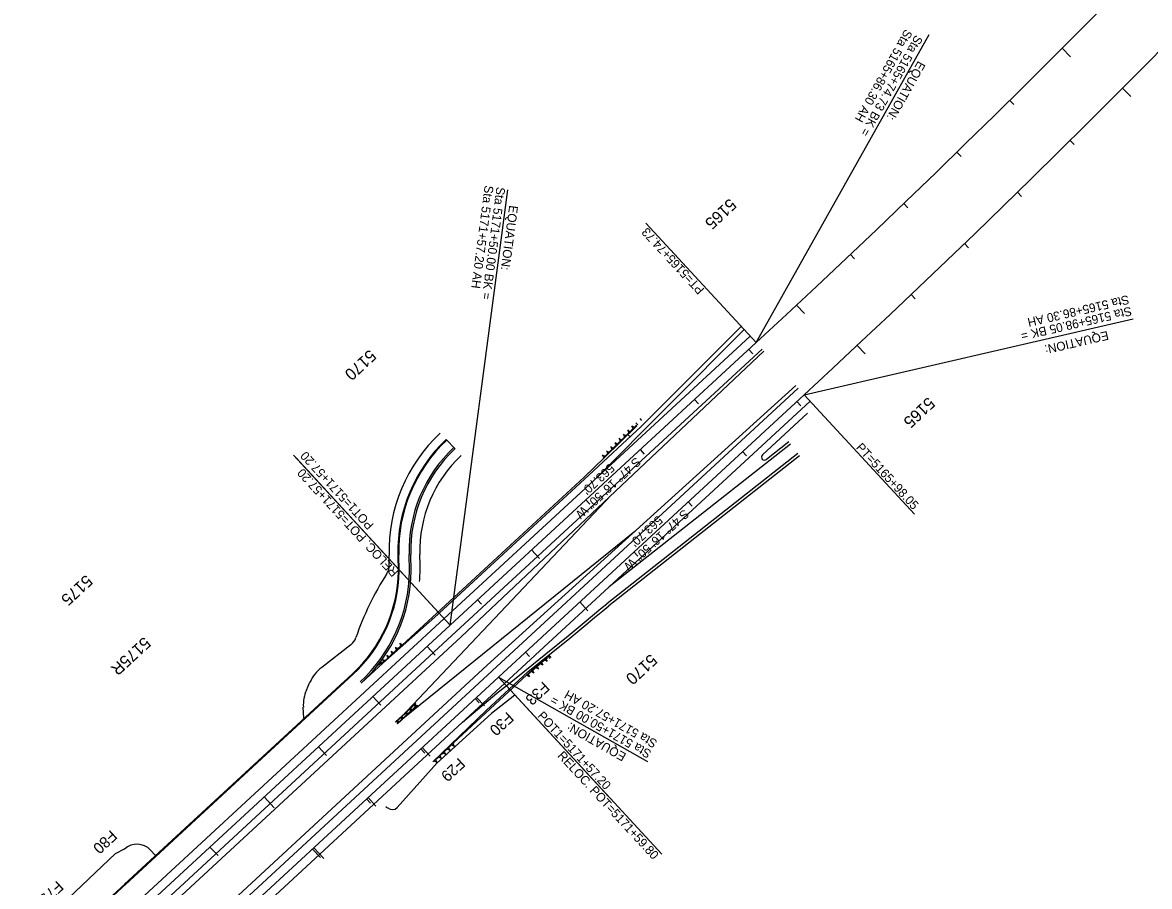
# Model space of a CAD drawing. Extents: x 2160877 to 2175861, y 601747 to 617724.
# Drawn here: x 2171628 to 2173154, y 613421 to 614591 of the extents above; entities that cross this region are included whole.
import ezdxf

# ---------------------------------------------------------------- set-up
doc = ezdxf.new("R2010")
doc.units = 0
for name, color, linetype in [('RD_HC_Cl', 7, 'Continuous'), ('RD_HC_CL_Rel', 7, 'Continuous'), ('RD_HC_Data', 7, 'Continuous'), ('RD_HC_Data_Rel', 7, 'Continuous'), ('RD_HC_Data_Tic', 7, 'Continuous'), ('RD_HC_Data_Tic_Rel', 7, 'Continuous'), ('RD_HC_TX_Rel_Sta50', 7, 'Continuous'), ('RD_HC_TX_StaOther', 7, 'Continuous'), ('RD_PD_CstnLmt', 7, 'Continuous'), ('RD_PD_CstnLmt_TX', 7, 'Continuous'), ('RD_PD_Final_LnLine', 7, 'Continuous'), ('RD_PD_Final_TrvlWay', 7, 'Continuous'), ('RD_PD_GR', 7, 'Continuous'), ('RD_PD_MedBWall', 7, 'Continuous')]:
    doc.layers.add(name, color=color, linetype=linetype)

msp = doc.modelspace()

# ---------------------------------------------------------------- linework, layer by layer
at = {"layer": 'RD_HC_Cl'}
for p, q in [((2172621.5, 614157.6), (2172207.3, 613775.1)), ((2172686.6, 614087), (2172272.5, 613704.6)), ((2172207.3, 613775.1), (2163672.2, 605893.8)), ((2172272.5, 613704.6), (2163737.4, 605823.3))]:
    msp.add_line(p, q, dxfattribs=at)
for radius, end in [(14276, 327.03525), (14372, 326.23563)]:
    msp.add_arc((2162936.5, 624645.9), radius, 312.71947, end, dxfattribs=at)
at = {"layer": 'RD_HC_CL_Rel'}
for p, q in [((2172207.3, 613775.1), (2171340.7, 612974.9)), ((2172272.5, 613704.6), (2170771.4, 612318.6))]:
    msp.add_line(p, q, dxfattribs=at)
at = {"layer": 'RD_HC_Data'}
for p, q in [((2172621.5, 614157.6), (2172855.6, 614574.5)), ((2172207.3, 613775.1), (2172285.1, 614364.1)), ((2172621.5, 614157.6), (2172472.2, 614319.2)), ((2172686.6, 614087), (2173132, 614189.8)), ((2172686.6, 614087), (2172836, 613925.2)), ((2172207.3, 613775.1), (2171994.9, 614005.2)), ((2172272.5, 613704.6), (2172474.3, 613590.3)), ((2172272.5, 613704.6), (2172421.7, 613543))]:
    msp.add_line(p, q, dxfattribs=at)
at = {"layer": 'RD_HC_Data_Rel'}
for p, q in [((2172207.3, 613775.1), (2171998.5, 614001.3)), ((2172272.5, 613704.6), (2172493.8, 613464.9))]:
    msp.add_line(p, q, dxfattribs=at)
at = {"layer": 'RD_HC_Data_Tic'}
for p, q in [((2173035.7, 614555.9), (2173047.1, 614544.5)), ((2173117.4, 614501.8), (2173128.7, 614490.5)), ((2172964.8, 614485.4), (2172970.4, 614479.7)), ((2173046.6, 614431.2), (2173052.2, 614425.5)), ((2172893.4, 614415.4), (2172899, 614409.6)), ((2172975.3, 614361.1), (2172980.8, 614355.4)), ((2172821.5, 614345.9), (2172827, 614340.1)), ((2172903.5, 614291.5), (2172909, 614285.7)), ((2172749.1, 614276.9), (2172754.6, 614271.1)), ((2172831.2, 614222.4), (2172836.7, 614216.6)), ((2172676.2, 614208.4), (2172687.2, 614196.7)), ((2172758.4, 614153.8), (2172769.3, 614142.1)), ((2172611.4, 614148.3), (2172616.8, 614142.4)), ((2172537.9, 614080.4), (2172543.4, 614074.5)), ((2172676.5, 614077.7), (2172682, 614071.9)), ((2172464.5, 614012.6), (2172469.9, 614006.7)), ((2172603.1, 614009.9), (2172608.5, 614004)), ((2172391, 613944.7), (2172396.4, 613938.9)), ((2172529.6, 613942.1), (2172535, 613936.2)), ((2172317.5, 613876.9), (2172328.4, 613865.1)), ((2172456.1, 613874.2), (2172461.5, 613868.3)), ((2172244.1, 613809.1), (2172249.5, 613803.2)), ((2172382.7, 613806.4), (2172393.5, 613794.6)), ((2172175.9, 613746.1), (2172181.3, 613740.2)), ((2172309.2, 613738.5), (2172314.6, 613732.7)), ((2172102.4, 613678.3), (2172107.8, 613672.4)), ((2172241, 613675.6), (2172246.4, 613669.7)), ((2172028.9, 613610.4), (2172034.4, 613604.5)), ((2172167.5, 613607.7), (2172173, 613601.9)), ((2171955.5, 613542.6), (2171966.3, 613530.8)), ((2172094.1, 613539.9), (2172099.5, 613534)), ((2171882, 613474.7), (2171887.4, 613468.9)), ((2172020.6, 613472.1), (2172031.5, 613460.3))]:
    msp.add_line(p, q, dxfattribs=at)
at = {"layer": 'RD_HC_Data_Tic_Rel'}
for p, q in [((2172175.9, 613746.1), (2172186.7, 613734.4)), ((2172102.4, 613678.3), (2172113.3, 613666.5)), ((2172242.9, 613677.3), (2172253.8, 613665.6)), ((2172028.9, 613610.4), (2172039.8, 613598.7)), ((2172169.4, 613609.5), (2172180.3, 613597.7)), ((2171955.5, 613542.6), (2171969, 613527.9)), ((2172096, 613541.7), (2172106.8, 613529.9)), ((2171882, 613474.7), (2171892.9, 613463)), ((2172022.5, 613473.8), (2172036.1, 613459.1))]:
    msp.add_line(p, q, dxfattribs=at)
at = {"layer": 'RD_PD_CstnLmt'}
for p, q in [((2172124.8, 613856.2), (2172124.5, 613869.7)), ((2172166.4, 613856.6), (2172166.1, 613870.7)), ((2172072.6, 613748.5), (2172033.5, 613717.8)), ((2172012.7, 613687), (2172017.4, 613697.8)), ((2172294.8, 613680.4), (2172263.1, 613655.5)), ((2172009.3, 613648.9), (2172008.4, 613664.1)), ((2172263.1, 613655.5), (2172189.1, 613588.3)), ((2172135.6, 613528.1), (2172189.1, 613588.3)), ((2172120, 613529.7), (2172122.6, 613527.6)), ((2171754.2, 613465.7), (2171681.6, 613397)), ((2171754.2, 613465.7), (2171766.2, 613472)), ((2171807.8, 613463.6), (2171801.4, 613470.5))]:
    msp.add_line(p, q, dxfattribs=at)
for centre, radius, start, end in [((2172343.7, 613875.1), 219.3, 133.1773, 181.4209), ((2172343.7, 613875.1), 177.7, 133.1773, 181.4209), ((2172104.8, 613855.7), 20, 327.0543, 1.4209), ((2171944.2, 613851.1), 222.3, 355.5815, 1.4209), ((2172447.7, 613633.5), 388.6, 147.0543, 161.2766), ((2172060.7, 613764.6), 20, 306.2944, 341.2766), ((2172063.1, 613677.5), 50, 126.2944, 156.1048), ((2172058.4, 613666.8), 50, 156.1048, 183.118), ((2172128.8, 613535.4), 10, 231.8554, 312.7195), ((2171783.1, 613453.5), 25, 42.7195, 132.3521)]:
    msp.add_arc(centre, radius, start, end, dxfattribs=at)
at = {"layer": 'RD_PD_Final_LnLine'}
for p, q in [((2172605.3, 614175.1), (2172401.6, 613970.8)), ((2172613.3, 614166.4), (2172401.6, 613970.8)), ((2172629.6, 614148.7), (2172215.5, 613766.3)), ((2172678.5, 614095.8), (2172264.3, 613713.4)), ((2172694.7, 614078.2), (2172422.5, 613826.8)), ((2172668, 614019.9), (2172422.5, 613826.8)), ((2172677.9, 614007.4), (2172419.4, 613804.1)), ((2172401.6, 613970.8), (2172199.2, 613784)), ((2172425.3, 613950.8), (2172140.7, 613650.6)), ((2172457.4, 613901.8), (2172143, 613648.1)), ((2172422.5, 613826.8), (2172222.3, 613642.1)), ((2172199.2, 613784), (2171332.6, 612983.8)), ((2172215.5, 613766.3), (2171348.9, 612966.1)), ((2172115.9, 613723.4), (2172086.9, 613696.6)), ((2172114.3, 613725.1), (2172108.2, 613719.4)), ((2172114.3, 613725.1), (2172115.9, 613723.4)), ((2172264.3, 613713.4), (2170763.3, 612327.4)), ((2172224.1, 613643.7), (2170779.6, 612309.8))]:
    msp.add_line(p, q, dxfattribs=at)
msp.add_lwpolyline([(2172224.1, 613643.7), (2172270.5, 613682.8), (2172284.9, 613694.4), (2172308.1, 613713.2), (2172336.9, 613736.4), (2172366.9, 613760.6), (2172388.6, 613778.6), (2172400.1, 613788.2), (2172411.3, 613797.7), (2172419.4, 613804.1)], dxfattribs=at)
at = {"layer": 'RD_PD_Final_TrvlWay'}
for p, q in [((2172601.2, 614179.5), (2172466, 614044)), ((2172632, 614146.1), (2172222.2, 613759)), ((2172675.3, 614099.3), (2172257.5, 613720.8)), ((2172691.2, 614061.8), (2172630.2, 614005.4)), ((2172466, 614044), (2172394.8, 613978.2)), ((2172665.6, 614023.1), (2172635.4, 613999.3)), ((2172680.4, 614004.2), (2172422.2, 613801.1)), ((2172394.8, 613978.2), (2172192.4, 613791.3)), ((2172190.4, 613789.4), (2172115.9, 613723.4)), ((2172192.4, 613791.3), (2172190.4, 613789.4)), ((2172222.2, 613759), (2171355.7, 612958.8)), ((2172257.5, 613720.8), (2170756.5, 612334.7)), ((2172312.6, 613711.7), (2172255.9, 613659.4)), ((2172255.9, 613659.4), (2172183.8, 613590.1))]:
    msp.add_line(p, q, dxfattribs=at)
msp.add_lwpolyline([(2172312.6, 613711.7), (2172369.4, 613757.5), (2172391.1, 613775.5), (2172402.7, 613785.2), (2172413.8, 613794.6), (2172422.2, 613801.1)], dxfattribs=at)
msp.add_arc((2172632.9, 614002.5), 4, 132.7195, 308.1849, dxfattribs=at)
at = {"layer": 'RD_PD_GR'}
for p, q in [((2172458.8, 614044.7), (2172415.3, 614001.9)), ((2172415.6, 614001.5), (2172459.8, 614045)), ((2172454.2, 614044.7), (2172452.9, 614043.5)), ((2172454.4, 614043.2), (2172453.5, 614044.1)), ((2172453.8, 614042.6), (2172455, 614043.8)), ((2172455, 614043.8), (2172456.4, 614042.4)), ((2172459.1, 614045.7), (2172458.4, 614045)), ((2172458.4, 614045), (2172458.8, 614044.7)), ((2172461.2, 614046.4), (2172458.6, 614049.1)), ((2172459.8, 614045), (2172459.1, 614045.7)), ((2172466.9, 614052), (2172464.3, 614054.7)), ((2172442.8, 614033.5), (2172441.5, 614032.2)), ((2172443, 614032), (2172442.1, 614032.9)), ((2172442.4, 614031.4), (2172443.6, 614032.6)), ((2172443.8, 614029.9), (2172442.4, 614031.4)), ((2172443.6, 614032.6), (2172445, 614031.2)), ((2172445, 614031.2), (2172443.8, 614029.9)), ((2172448.5, 614039.1), (2172447.2, 614037.9)), ((2172450.3, 614030.4), (2172447.7, 614033.1)), ((2172448.7, 614037.6), (2172447.8, 614038.5)), ((2172448.1, 614037), (2172449.3, 614038.2)), ((2172449.5, 614035.5), (2172448.1, 614037)), ((2172449.3, 614038.2), (2172450.7, 614036.8)), ((2172450.7, 614036.8), (2172449.5, 614035.5)), ((2172455.2, 614041.2), (2172453.8, 614042.6)), ((2172456.4, 614042.4), (2172455.2, 614041.2)), ((2172425.7, 614016.6), (2172424.4, 614015.4)), ((2172425.9, 614015.1), (2172425, 614016)), ((2172425.3, 614014.5), (2172426.5, 614015.7)), ((2172426.7, 614013.1), (2172425.3, 614014.5)), ((2172426.5, 614015.7), (2172427.9, 614014.3)), ((2172427.9, 614014.3), (2172426.7, 614013.1)), ((2172431.4, 614022.2), (2172430.1, 614021)), ((2172431.6, 614020.7), (2172430.7, 614021.6)), ((2172431, 614020.1), (2172432.2, 614021.4)), ((2172432.4, 614018.7), (2172431, 614020.1)), ((2172432.2, 614021.4), (2172433.6, 614019.9)), ((2172433.6, 614019.9), (2172432.4, 614018.7)), ((2172437.1, 614027.9), (2172435.8, 614026.6)), ((2172437.3, 614026.4), (2172436.4, 614027.2)), ((2172436.7, 614025.7), (2172437.9, 614027)), ((2172438.1, 614024.3), (2172436.7, 614025.7)), ((2172437.9, 614027), (2172439.3, 614025.5)), ((2172439.3, 614025.5), (2172438.1, 614024.3)), ((2172388.6, 613975.5), (2172415.6, 614001.5)), ((2172414.3, 614005.4), (2172413, 614004.2)), ((2172414.5, 614003.9), (2172413.6, 614004.8)), ((2172413.9, 614003.3), (2172415.1, 614004.5)), ((2172415.3, 614001.9), (2172413.9, 614003.3)), ((2172415.1, 614004.5), (2172416.5, 614003.1)), ((2172416.5, 614003.1), (2172415.3, 614001.9)), ((2172415.3, 614001.9), (2172415.6, 614001.5)), ((2172420, 614011), (2172418.7, 614009.8)), ((2172420.2, 614009.5), (2172419.3, 614010.4)), ((2172419.6, 614008.9), (2172420.8, 614010.1)), ((2172421, 614007.5), (2172419.6, 614008.9)), ((2172420.8, 614010.1), (2172422.2, 614008.7)), ((2172422.2, 614008.7), (2172421, 614007.5)), ((2172142.2, 613748), (2172388.6, 613975.5)), ((2172142.4, 613747.8), (2172115.9, 613723.4)), ((2172116.3, 613724.4), (2172142, 613748.2)), ((2172126.8, 613738.5), (2172128.1, 613739.7)), ((2172128.3, 613738.2), (2172127.4, 613739.1)), ((2172128.9, 613738.8), (2172127.6, 613737.6)), ((2172130.3, 613737.3), (2172128.9, 613738.8)), ((2172132.7, 613744), (2172133.9, 613745.1)), ((2172134.2, 613743.6), (2172133.3, 613744.6)), ((2172134.8, 613744.2), (2172133.5, 613743)), ((2172133.5, 613743), (2172134.9, 613741.6)), ((2172136.2, 613742.8), (2172134.8, 613744.2)), ((2172134.9, 613741.6), (2172136.2, 613742.8)), ((2172138.5, 613749.4), (2172139.8, 613750.6)), ((2172140, 613749.1), (2172139.2, 613750)), ((2172140.7, 613749.7), (2172139.4, 613748.5)), ((2172139.4, 613748.5), (2172140.7, 613747)), ((2172142, 613748.2), (2172140.7, 613749.7)), ((2172140.7, 613747), (2172142, 613748.2)), ((2172142, 613748.2), (2172142.4, 613747.8)), ((2172113, 613720.7), (2172110.4, 613723.4)), ((2172114.5, 613722), (2172111.9, 613724.8)), ((2172115, 613727.7), (2172116.3, 613728.9)), ((2172115.2, 613724.1), (2172116, 613724.8)), ((2172115.9, 613723.4), (2172115.2, 613724.1)), ((2172116.5, 613727.4), (2172115.7, 613728.3)), ((2172117.2, 613727.9), (2172115.9, 613726.8)), ((2172115.9, 613726.8), (2172117.2, 613725.3)), ((2172116, 613724.8), (2172116.3, 613724.4)), ((2172118.5, 613726.5), (2172117.2, 613727.9)), ((2172117.2, 613725.3), (2172118.5, 613726.5)), ((2172120.9, 613733.1), (2172122.2, 613734.3)), ((2172122.4, 613732.8), (2172121.6, 613733.7)), ((2172123, 613733.4), (2172121.8, 613732.2)), ((2172121.8, 613732.2), (2172123.1, 613730.7)), ((2172124.4, 613731.9), (2172123, 613733.4)), ((2172123.1, 613730.7), (2172124.4, 613731.9)), ((2172127.6, 613737.6), (2172129, 613736.1)), ((2172129, 613736.1), (2172130.3, 613737.3)), ((2172311.2, 613707.7), (2172338.3, 613731.4)), ((2172337.9, 613730.4), (2172311.5, 613707.3)), ((2172330.9, 613724.3), (2172329.6, 613723.1)), ((2172329.6, 613723.1), (2172330.9, 613721.6)), ((2172332.2, 613722.8), (2172330.9, 613724.3)), ((2172330.9, 613721.6), (2172332.2, 613722.8)), ((2172337, 613729.5), (2172335.6, 613728.4)), ((2172335.6, 613728.4), (2172336.9, 613726.9)), ((2172336.9, 613726.9), (2172338.3, 613728)), ((2172338.3, 613728), (2172337, 613729.5)), ((2172337.6, 613727.5), (2172338.4, 613726.5)), ((2172339.1, 613727.1), (2172337.8, 613725.9)), ((2172338.2, 613730), (2172337.9, 613730.4)), ((2172339, 613730.7), (2172338.2, 613730)), ((2172338.3, 613731.4), (2172339, 613730.7)), ((2172339.8, 613732.7), (2172342.3, 613729.9)), ((2172341.3, 613734), (2172343.8, 613731.2)), ((2172211.7, 613615.9), (2172311.2, 613707.7)), ((2172311.5, 613707.3), (2172311.2, 613707.7)), ((2172312.8, 613708.5), (2172311.5, 613707.3)), ((2172314.2, 613707), (2172312.8, 613708.5)), ((2172318.9, 613713.8), (2172317.6, 613712.6)), ((2172317.6, 613712.6), (2172318.9, 613711.1)), ((2172320.2, 613712.3), (2172318.9, 613713.8)), ((2172318.9, 613711.1), (2172320.2, 613712.3)), ((2172319.5, 613711.7), (2172320.4, 613710.7)), ((2172321, 613711.3), (2172319.7, 613710.2)), ((2172324.9, 613719), (2172323.6, 613717.9)), ((2172323.6, 613717.9), (2172324.9, 613716.4)), ((2172326.2, 613717.5), (2172324.9, 613719)), ((2172324.9, 613716.4), (2172326.2, 613717.5)), ((2172325.6, 613716.9), (2172326.4, 613716)), ((2172327, 613716.6), (2172325.7, 613715.4)), ((2172331.6, 613722.2), (2172332.4, 613721.3)), ((2172333.1, 613721.8), (2172331.7, 613720.7)), ((2172311.5, 613707.3), (2172312.8, 613705.8)), ((2172312.8, 613705.8), (2172314.2, 613707)), ((2172313.5, 613706.4), (2172314.3, 613705.5)), ((2172315, 613706.1), (2172313.7, 613704.9)), ((2172160.6, 613669.1), (2172133.4, 613644)), ((2172133.7, 613643.7), (2172160.9, 613668.8)), ((2172135.5, 613641.7), (2172162.7, 613666.8)), ((2172163.1, 613666.4), (2172135.9, 613641.3)), ((2172152, 613661.4), (2172153.3, 613662.6)), ((2172152.4, 613660.9), (2172153.7, 613662.1)), ((2172153.5, 613661), (2172152.7, 613662)), ((2172153.7, 613662.1), (2172155.1, 613660.7)), ((2172157.9, 613666.8), (2172159.2, 613668)), ((2172158.3, 613666.4), (2172159.6, 613667.6)), ((2172159.7, 613664.9), (2172158.3, 613666.4)), ((2172159.4, 613666.5), (2172158.6, 613667.4)), ((2172160.1, 613667.1), (2172158.8, 613665.9)), ((2172158.8, 613665.9), (2172160.1, 613664.4)), ((2172159.6, 613667.6), (2172161, 613666.1)), ((2172161, 613666.1), (2172159.7, 613664.9)), ((2172161.4, 613665.6), (2172160.1, 613667.1)), ((2172160.1, 613664.4), (2172161.4, 613665.6)), ((2172160.3, 613665.5), (2172161.2, 613664.6)), ((2172160.5, 613664), (2172161.8, 613665.2)), ((2172160.9, 613668.8), (2172160.6, 613669.1)), ((2172162.7, 613666.8), (2172163.1, 613666.4)), ((2172138.4, 613648), (2172138.1, 613648.3)), ((2172140.3, 613650.5), (2172141.6, 613651.7)), ((2172140.7, 613650.1), (2172142, 613651.3)), ((2172142, 613648.6), (2172140.7, 613650.1)), ((2172141.8, 613650.2), (2172140.9, 613651.1)), ((2172142.4, 613650.8), (2172141.1, 613649.6)), ((2172141.1, 613649.6), (2172142.5, 613648.1)), ((2172142, 613651.3), (2172143.3, 613649.8)), ((2172143.3, 613649.8), (2172142, 613648.6)), ((2172143.8, 613649.3), (2172142.4, 613650.8)), ((2172142.5, 613648.1), (2172143.8, 613649.3)), ((2172142.7, 613649.2), (2172143.5, 613648.3)), ((2172142.9, 613647.7), (2172144.2, 613648.9)), ((2172146.2, 613655.9), (2172147.5, 613657.1)), ((2172146.6, 613655.5), (2172147.9, 613656.7)), ((2172147.9, 613654), (2172146.6, 613655.5)), ((2172147.7, 613655.6), (2172146.8, 613656.5)), ((2172148.3, 613656.2), (2172147, 613655)), ((2172147, 613655), (2172148.4, 613653.6)), ((2172147.9, 613656.7), (2172149.2, 613655.2)), ((2172149.2, 613655.2), (2172147.9, 613654)), ((2172149.7, 613654.7), (2172148.3, 613656.2)), ((2172148.4, 613653.6), (2172149.7, 613654.7)), ((2172148.6, 613654.6), (2172149.4, 613653.7)), ((2172148.8, 613653.1), (2172150.1, 613654.3)), ((2172153.8, 613659.5), (2172152.4, 613660.9)), ((2172154.2, 613661.6), (2172152.9, 613660.5)), ((2172152.9, 613660.5), (2172154.3, 613659)), ((2172155.1, 613660.7), (2172153.8, 613659.5)), ((2172155.5, 613660.2), (2172154.2, 613661.6)), ((2172154.3, 613659), (2172155.5, 613660.2)), ((2172154.4, 613660.1), (2172155.3, 613659.2)), ((2172154.6, 613658.6), (2172155.9, 613659.7)), ((2172133.4, 613644), (2172133.7, 613643.7)), ((2172134.4, 613645.1), (2172135.7, 613646.3)), ((2172134.8, 613644.7), (2172136.1, 613645.9)), ((2172136.2, 613643.2), (2172134.8, 613644.7)), ((2172135.9, 613644.8), (2172135.1, 613645.7)), ((2172136.5, 613645.4), (2172135.3, 613644.2)), ((2172135.3, 613644.2), (2172136.6, 613642.7)), ((2172135.9, 613641.3), (2172135.5, 613641.7)), ((2172136.1, 613645.9), (2172137.5, 613644.4)), ((2172137.5, 613644.4), (2172136.2, 613643.2)), ((2172137.9, 613643.9), (2172136.5, 613645.4)), ((2172136.6, 613642.7), (2172137.9, 613643.9)), ((2172136.8, 613643.8), (2172137.7, 613642.9)), ((2172137, 613642.3), (2172138.3, 613643.5)), ((2172140.2, 613646), (2172140.5, 613645.6)), ((2172211.8, 613615.9), (2172184.6, 613590.8)), ((2172184.9, 613590.4), (2172212.1, 613615.5)), ((2172197.8, 613602.3), (2172199, 613603.5)), ((2172199.1, 613600.8), (2172197.8, 613602.3)), ((2172199, 613603.5), (2172200.4, 613602)), ((2172200.4, 613602), (2172199.1, 613600.8)), ((2172199.8, 613601.4), (2172200.6, 613600.5)), ((2172200, 613599.9), (2172201.3, 613601.1)), ((2172203.6, 613607.7), (2172204.9, 613608.9)), ((2172205, 613606.3), (2172203.6, 613607.7)), ((2172204.9, 613608.9), (2172206.3, 613607.4)), ((2172206.3, 613607.4), (2172205, 613606.3)), ((2172205.6, 613606.8), (2172206.5, 613605.9)), ((2172205.8, 613605.3), (2172207.1, 613606.5)), ((2172209.5, 613613.1), (2172210.8, 613614.3)), ((2172210.9, 613611.7), (2172209.5, 613613.1)), ((2172210.8, 613614.3), (2172212.2, 613612.9)), ((2172212.2, 613612.9), (2172210.9, 613611.7)), ((2172211.5, 613612.3), (2172212.4, 613611.4)), ((2172211.7, 613610.8), (2172213, 613611.9)), ((2172212.1, 613615.5), (2172211.8, 613615.9)), ((2172184.6, 613590.8), (2172184.9, 613590.4)), ((2172186, 613591.4), (2172187.3, 613592.6)), ((2172187.4, 613590), (2172186, 613591.4)), ((2172187.3, 613592.6), (2172188.6, 613591.2)), ((2172188.6, 613591.2), (2172187.4, 613590)), ((2172188, 613590.6), (2172188.9, 613589.6)), ((2172188.2, 613589.1), (2172189.5, 613590.2)), ((2172189.6, 613594.7), (2172189.2, 613595.1)), ((2172191.9, 613596.9), (2172193.2, 613598.1)), ((2172193.2, 613595.4), (2172191.9, 613596.9)), ((2172193.2, 613598.1), (2172194.5, 613596.6)), ((2172194.5, 613596.6), (2172193.2, 613595.4)), ((2172193.9, 613596), (2172194.7, 613595.1)), ((2172194.1, 613594.5), (2172195.4, 613595.7))]:
    msp.add_line(p, q, dxfattribs=at)
at = {"layer": 'RD_PD_MedBWall'}
for p, q in [((2172201.9, 614026.3), (2172213.8, 614013.6)), ((2172137.2, 613848.1), (2172136.6, 613870.2)), ((2172138.2, 613848.1), (2172137.6, 613870.2)), ((2172152.2, 613848.2), (2172151.6, 613870.5)), ((2172154.5, 613848.4), (2172153.9, 613870.6)), ((2172075.1, 613709.3), (2171312.7, 613005.3)), ((2172075.8, 613708.6), (2171313.4, 613004.6)), ((2172064.3, 613699.3), (2171766.5, 613424.3)), ((2172065, 613698.6), (2171767.2, 613423.6))]:
    msp.add_line(p, q, dxfattribs=at)
for centre, radius, start, end in [((2172343.5, 613875.3), 207, 133.1773, 181.4209), ((2172343.5, 613875.3), 206, 133.1773, 181.4209), ((2172343.5, 613875.3), 192, 133.1773, 181.4209), ((2172343.5, 613875.3), 189.7, 133.1773, 181.4209), ((2171944.2, 613851.1), 193, 312.7195, 359.12), ((2171944.2, 613851.1), 194, 312.7195, 359.1259), ((2171944.2, 613851.1), 208, 312.7195, 359.2045), ((2171944.2, 613851.1), 210.3, 312.7195, 359.2641)]:
    msp.add_arc(centre, radius, start, end, dxfattribs=at)

# ---------------------------------------------------------------- texts
at = {"layer": 'RD_HC_Data'}
for s, rotation, p in [('Sta 5165+86.30 AH', 240.6833, (2172823.3, 614582.6)), ('Sta 5165+74.73 BK = ', 240.6833, (2172837.3, 614574.8)), ('EQUATION:', 240.6833, (2172840.9, 614539.6)), ('Sta 5171+57.20 AH', 262.4748, (2172254.1, 614370.8)), ('Sta 5171+50.00 BK = ', 262.4748, (2172270, 614368.7)), ('EQUATION:', 262.4748, (2172287.3, 614343.8)), ('PT=5165+74.73', 132.7195, (2172552.2, 614229.7)), ('Sta 5165+86.30 AH', 192.9905, (2173124.9, 614221.9)), ('Sta 5165+98.05 BK = ', 192.9905, (2173128.5, 614206.3)), ('EQUATION:', 192.9905, (2173097.1, 614173.4)), ('PT=5165+98.05', 312.7195, (2172755.9, 614014.9)), ('POT1=5171+57.20', 132.7195, (2172104.7, 613911.1)), ('Sta 5171+50.00 BK = ', 150.4677, (2172480.8, 613604.4)), ('Sta 5171+57.20 AH', 150.4677, (2172488.7, 613618.3)), ('POT1=5171+57.20', 312.7195, (2172324.6, 613651.5)), ('EQUATION:', 150.4677, (2172446.6, 613600.5))]:
    msp.add_text(s, height=12, rotation=rotation, dxfattribs=at).set_placement(p)
at = {"layer": 'RD_HC_Data_Rel'}
for s, rotation, p in [('RELOC. POT=5171+57.20', 132.7195, (2172138, 613847.3)), ('RELOC. POT=5171+59.80', 312.7195, (2172351.8, 613597.6))]:
    msp.add_text(s, height=12, rotation=rotation, dxfattribs=at).set_placement(p)
at = {"layer": 'RD_HC_TX_Rel_Sta50'}
msp.add_text('5175R', height=16, rotation=222.7195, dxfattribs=at).set_placement((2171792.7, 613760.1))
at = {"layer": 'RD_HC_TX_StaOther'}
for s, height, rotation, p in [('5165', 16, 223.0194, (2172585.6, 614353.6)), ('5170', 16, 222.7195, (2172098, 614149)), ('5165', 16, 223.1104, (2172854.4, 614084.7)), ('S 47%%d 16\' 50" W', 12, 222.7195, (2172458.6, 614003.1)), ("563.70'", 12, 222.7195, (2172423, 613994.7)), ('S 47%%d 16\' 50" W', 12, 222.7195, (2172523.8, 613932.6)), ("563.70'", 12, 222.7195, (2172488.2, 613924.2)), ('5175', 16, 222.7195, (2171714, 613844.1)), ('5170', 16, 222.7195, (2172478.5, 613737))]:
    msp.add_text(s, height=height, rotation=rotation, dxfattribs=at).set_placement(p)
at = {"layer": 'RD_PD_CstnLmt_TX'}
for s, p in [('F33', (2172333.2, 613699.7)), ('F30', (2172284.7, 613658.4)), ('F29', (2172218.9, 613596.3)), ('F80', (2171747.7, 613498.6)), ('F79', (2171675.1, 613429.9))]:
    msp.add_text(s, height=15, rotation=222.7195, dxfattribs=at).set_placement(p)

doc.saveas('drawing.dxf')
